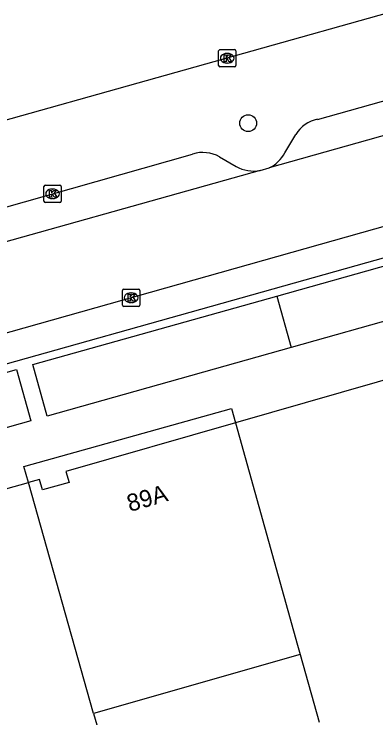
# Model space of a CAD drawing. Extents: x 159689 to 160786, y 387323 to 388339.
# Drawn here: x 159923.73 to 159944.8, y 388203.42 to 388244.36 of the extents above; entities that cross this region are included whole.
import ezdxf

# ---------------------------------------------------------------- set-up
doc = ezdxf.new("R2010")
doc.units = 0
for name, color, linetype in [('IMGEO_Boom', 7, 'Continuous'), ('IMGEO_Kolk', 7, 'Continuous'), ('IMGEO_Pand', 7, 'Continuous'), ('IMGEO_Pand_nummerreeks', 7, 'Continuous'), ('IMGEO_Parkeervlak_open', 7, 'Continuous'), ('IMGEO_Rijbaan_lokaal_open', 7, 'Continuous'), ('IMGEO_Rijbaan_regionaal_gesloten', 7, 'Continuous'), ('IMGEO_Voetpad_open', 7, 'Continuous')]:
    doc.layers.add(name, color=color, linetype=linetype)

msp = doc.modelspace()

# ---------------------------------------------------------------- linework, layer by layer
at = {"layer": 'IMGEO_Boom'}
msp.add_circle((159937.36, 388238.014), 0.489, dxfattribs=at)
at = {"layer": 'IMGEO_Kolk'}
for p, q in [((159935.64, 388241.362), (159935.64, 388242.214)), ((159935.715, 388242.288), (159936.567, 388242.288)), ((159936.641, 388242.214), (159936.641, 388241.362)), ((159936.128, 388242.068), (159936.153, 388242.068)), ((159936.151, 388241.508), (159936.126, 388241.508)), ((159936.567, 388241.288), (159935.715, 388241.288)), ((159925.543, 388234.402), (159926.395, 388234.402)), ((159925.468, 388233.476), (159925.468, 388234.328)), ((159925.956, 388234.182), (159925.981, 388234.182)), ((159926.469, 388234.328), (159926.469, 388233.476)), ((159925.979, 388233.622), (159925.954, 388233.622)), ((159926.395, 388233.402), (159925.543, 388233.402)), ((159930.047, 388227.431), (159930.047, 388228.283)), ((159930.122, 388228.357), (159930.974, 388228.357)), ((159931.048, 388228.283), (159931.048, 388227.431)), ((159930.535, 388228.137), (159930.56, 388228.137)), ((159930.558, 388227.577), (159930.533, 388227.577)), ((159930.974, 388227.357), (159930.122, 388227.357))]:
    msp.add_line(p, q, dxfattribs=at)
for points in [[(159935.64, 388241.362), (159935.64, 388242.214)], [(159935.715, 388242.288), (159936.567, 388242.288)], [(159936.641, 388242.214), (159936.641, 388241.362)], [(159935.961, 388241.988), (159936.084, 388241.988), (159936.084, 388241.837), (159936.214, 388241.988), (159936.378, 388241.988), (159936.232, 388241.837), (159936.385, 388241.588), (159936.233, 388241.588), (159936.148, 388241.752), (159936.084, 388241.685), (159936.084, 388241.588), (159935.961, 388241.588), (159935.961, 388241.988)], [(159936.567, 388241.288), (159935.715, 388241.288)], [(159925.543, 388234.402), (159926.395, 388234.402)], [(159925.468, 388233.476), (159925.468, 388234.328)], [(159925.789, 388234.102), (159925.912, 388234.102), (159925.912, 388233.951), (159926.042, 388234.102), (159926.206, 388234.102), (159926.06, 388233.951), (159926.213, 388233.702), (159926.061, 388233.702), (159925.976, 388233.866), (159925.912, 388233.799), (159925.912, 388233.702), (159925.789, 388233.702), (159925.789, 388234.102)], [(159926.469, 388234.328), (159926.469, 388233.476)], [(159926.395, 388233.402), (159925.543, 388233.402)], [(159930.047, 388227.431), (159930.047, 388228.283)], [(159930.122, 388228.357), (159930.974, 388228.357)], [(159931.048, 388228.283), (159931.048, 388227.431)], [(159930.368, 388228.057), (159930.491, 388228.057), (159930.491, 388227.906), (159930.621, 388228.057), (159930.785, 388228.057), (159930.639, 388227.906), (159930.792, 388227.657), (159930.64, 388227.657), (159930.555, 388227.821), (159930.491, 388227.754), (159930.491, 388227.657), (159930.368, 388227.657), (159930.368, 388228.057)], [(159930.974, 388227.357), (159930.122, 388227.357)]]:
    msp.add_lwpolyline(points, dxfattribs=at)
for centre, start, end in [((159935.717, 388242.212), 91.552, 178.448), ((159935.717, 388242.212), 91.552, 178.448), ((159936.565, 388242.212), 1.552, 88.448), ((159936.565, 388242.212), 1.552, 88.448), ((159935.717, 388241.364), 181.552, 268.448), ((159935.717, 388241.364), 181.552, 268.448), ((159936.565, 388241.364), 271.552, 358.448), ((159936.565, 388241.364), 271.552, 358.448), ((159925.545, 388234.326), 91.552, 178.448), ((159925.545, 388234.326), 91.552, 178.448), ((159926.393, 388234.326), 1.552, 88.448), ((159926.393, 388234.326), 1.552, 88.448), ((159925.545, 388233.478), 181.552, 268.448), ((159925.545, 388233.478), 181.552, 268.448), ((159926.393, 388233.478), 271.552, 358.448), ((159926.393, 388233.478), 271.552, 358.448), ((159930.124, 388228.281), 91.552, 178.448), ((159930.124, 388228.281), 91.552, 178.448), ((159930.972, 388228.281), 1.552, 88.448), ((159930.972, 388228.281), 1.552, 88.448), ((159930.124, 388227.433), 181.552, 268.448), ((159930.124, 388227.433), 181.552, 268.448), ((159930.972, 388227.433), 271.552, 358.448), ((159930.972, 388227.433), 271.552, 358.448)]:
    msp.add_arc(centre, 0.0765, start, end, dxfattribs=at)
for centre, major_axis, ratio, start_param, end_param in [((159936.127, 388241.788), (-0.387, 0.002), 0.722429, 4.712389, 7.853982), ((159936.152, 388241.788), (-0.39, 0.002), 0.717154, 1.570796, 4.712389), ((159925.955, 388233.902), (-0.387, 0.002), 0.722429, 4.712389, 7.853982), ((159925.98, 388233.902), (-0.39, 0.002), 0.717154, 1.570796, 4.712389), ((159930.534, 388227.857), (-0.387, 0.002), 0.722429, 4.712389, 7.853982), ((159930.559, 388227.857), (-0.39, 0.002), 0.717154, 1.570796, 4.712389)]:
    msp.add_ellipse(centre, major_axis=major_axis, ratio=ratio, start_param=start_param, end_param=end_param, dxfattribs=at)
at = {"layer": 'IMGEO_Pand'}
for points in [[(159951.029, 388224.71), (159936.622, 388220.583)], [(159936.622, 388220.583), (159926.75, 388217.753), (159926.929, 388217.11), (159925.382, 388216.68), (159925.212, 388217.294), (159924.56, 388217.113)], [(159936.622, 388220.583), (159940.238, 388207.656), (159940.393, 388207.1)], [(159920.726, 388216.048), (159924.56, 388217.113)], [(159928.356, 388203.671), (159924.56, 388217.113)], [(159940.393, 388207.1), (159928.356, 388203.671)], [(159940.393, 388207.1), (159941.49, 388203.168)], [(159928.356, 388203.671), (159929.499, 388199.78), (159929.781, 388199.86)]]:
    msp.add_lwpolyline(points, dxfattribs=at)
at = {"layer": 'IMGEO_Parkeervlak_open'}
for points in [[(159941.402, 388238.234), (159945.748, 388239.45), (159950.261, 388240.714), (159954.649, 388241.944)], [(159939.503, 388236.288), (159940.128, 388237.353)], [(159921.449, 388232.625), (159934.124, 388236.216)], [(159935.689, 388236.053), (159936.661, 388235.487)]]:
    msp.add_lwpolyline(points, dxfattribs=at)
for centre, radius, start, end in [((159941.752, 388236.366), 1.901, 100.6232, 148.7063), ((159934.715, 388234.295), 2.01, 61.0135, 107.0942), ((159937.611, 388237.343), 2.166, 296.8394, 330.8589), ((159937.687, 388237.379), 2.152, 241.5403, 279.908)]:
    msp.add_arc(centre, radius, start, end, dxfattribs=at)
at = {"layer": 'IMGEO_Rijbaan_lokaal_open'}
for points in [[(159858.217, 388207.473), (159948.035, 388232.803), (159952.178, 388233.968), (160000, 388247.417), (160009.184, 388250), (160038.617, 388258.278)], [(159958.522, 388241.005), (159950.795, 388238.836), (159938.589, 388235.41)], [(159938.057, 388235.259), (159918.811, 388229.861)], [(159938.057, 388235.259), (159938.589, 388235.41)]]:
    msp.add_lwpolyline(points, dxfattribs=at)
at = {"layer": 'IMGEO_Rijbaan_regionaal_gesloten'}
msp.add_lwpolyline([(159919.6, 388237.172), (159948.924, 388245.417), (160022.709, 388266.163)], dxfattribs=at)
at = {"layer": 'IMGEO_Voetpad_open'}
for points in [[(159946.829, 388230.64), (159946.592, 388230.541), (159911.774, 388220.768)], [(159939.021, 388227.946), (159945.654, 388229.804)], [(159939.859, 388224.967), (159925.664, 388220.973), (159924.821, 388223.967), (159939.021, 388227.946)], [(159939.021, 388227.946), (159939.859, 388224.967)], [(159946.49, 388226.833), (159939.859, 388224.967)], [(159924.705, 388220.707), (159918.058, 388218.833), (159917.222, 388221.801), (159923.868, 388223.676), (159924.705, 388220.707)], [(159924.56, 388217.113), (159924.3, 388218.048), (159936.392, 388221.407), (159936.622, 388220.583)]]:
    msp.add_lwpolyline(points, dxfattribs=at)

# ---------------------------------------------------------------- texts
at = {"layer": 'IMGEO_Pand_nummerreeks'}
msp.add_text('89A', height=1, rotation=16.0745, dxfattribs=at).set_placement((159930.468, 388215.395))

doc.saveas('drawing.dxf')
